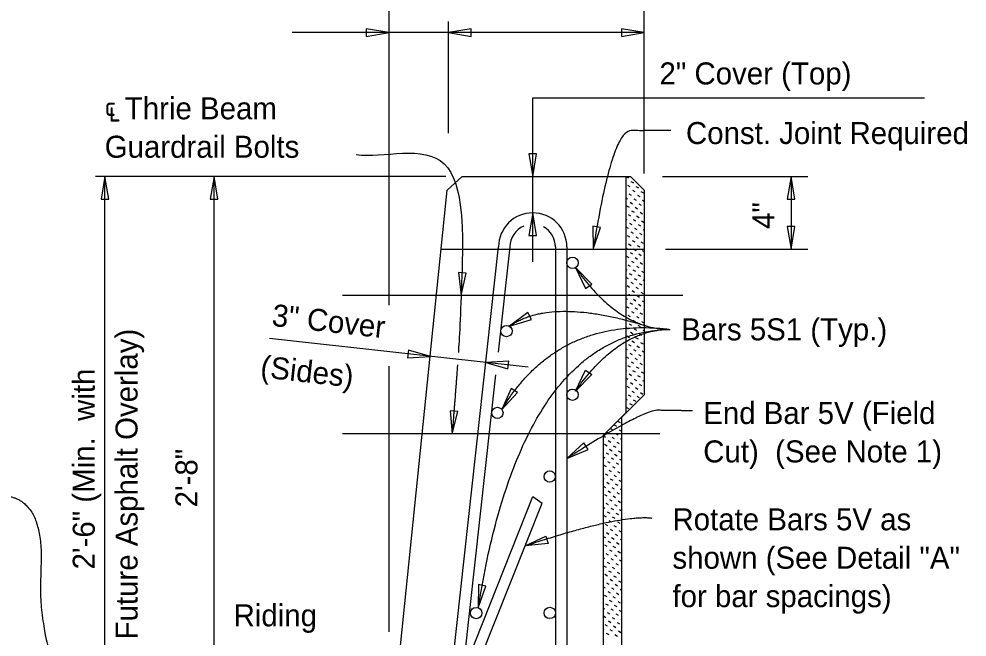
# Model space of a CAD drawing. Extents: x 120632.7 to 120668.8, y 120715.7 to 120740.6.
# Drawn here: x 120645.927 to 120650.27, y 120724.135 to 120726.967 of the extents above; entities that cross this region are included whole.
import ezdxf

# ---------------------------------------------------------------- set-up
doc = ezdxf.new("R2010")
doc.units = 0
for name, color, linetype in [('CL_Minor', 7, 'Continuous'), ('Dimension', 7, 'Continuous'), ('Miscellaneous', 7, 'Continuous'), ('Rebar', 7, 'Continuous'), ('TextStructures', 7, 'Continuous'), ('TrafBarrierConc', 7, 'Continuous')]:
    doc.layers.add(name, color=color, linetype=linetype)

msp = doc.modelspace()

# ---------------------------------------------------------------- linework, layer by layer
at = {"layer": 'CL_Minor'}
for p, q in [((120648.9674, 120725.6995), (120647.4083, 120725.6995)), ((120648.8627, 120725.0664), (120647.4083, 120725.0664))]:
    msp.add_line(p, q, dxfattribs=at)
at = {"layer": 'Dimension'}
for p, q in [((120648.7907, 120726.2582), (120648.7907, 120727.3935)), ((120647.6221, 120725.6558), (120647.6221, 120727.38)), ((120647.8948, 120726.4428), (120647.8948, 120726.9548)), ((120648.7907, 120726.9043), (120647.1778, 120726.9043)), ((120648.2804, 120725.8538), (120648.2804, 120726.6046)), ((120648.2804, 120726.6046), (120650.0749, 120726.6046)), ((120647.8818, 120726.2451), (120646.2774, 120726.2451)), ((120646.3205, 120722.7748), (120646.3205, 120726.2451)), ((120646.8205, 120723.5784), (120646.8205, 120726.2451)), ((120648.8745, 120726.2451), (120649.5403, 120726.2451)), ((120649.4639, 120726.2451), (120649.4639, 120725.9118)), ((120648.888, 120725.9118), (120649.5403, 120725.9118)), ((120648.26, 120725.3711), (120647.0749, 120725.5022)), ((120647.6221, 120724.1579), (120647.6221, 120725.3756))]:
    msp.add_line(p, q, dxfattribs=at)
for points in [[(120647.6221, 120726.9043), (120647.518, 120726.922), (120647.518, 120726.8867)], [(120647.8948, 120726.9043), (120647.999, 120726.8867), (120647.999, 120726.922)], [(120648.7907, 120726.9043), (120648.6866, 120726.922), (120648.6866, 120726.8867)], [(120648.2803, 120726.2451), (120648.298, 120726.3492), (120648.2627, 120726.3492)], [(120646.3205, 120726.2451), (120646.3029, 120726.141), (120646.3382, 120726.141)], [(120646.8205, 120726.2451), (120646.8029, 120726.141), (120646.8382, 120726.141)], [(120649.4639, 120726.2451), (120649.4463, 120726.141), (120649.4815, 120726.141)], [(120648.2803, 120726.0784), (120648.2627, 120725.9743), (120648.298, 120725.9743)], [(120648.5572, 120725.9118), (120648.5909, 120726.0119), (120648.556, 120726.0174)], [(120649.4639, 120725.9118), (120649.4815, 120726.0159), (120649.4463, 120726.0159)], [(120647.9523, 120725.6995), (120647.9759, 120725.8025), (120647.9407, 120725.8045)], [(120648.4766, 120725.8273), (120648.5215, 120725.7317), (120648.5505, 120725.7519)], [(120648.1733, 120725.559), (120648.2744, 120725.5897), (120648.2586, 120725.6213)], [(120647.8126, 120725.4206), (120647.711, 120725.4493), (120647.7072, 120725.4142)], [(120648.0655, 120725.3927), (120648.167, 120725.3636), (120648.1709, 120725.3986)], [(120648.4766, 120725.2619), (120648.5215, 120725.3574), (120648.5505, 120725.3373)], [(120648.1389, 120725.1777), (120648.2112, 120725.2547), (120648.1819, 120725.2742)], [(120647.9113, 120725.0664), (120647.937, 120725.1688), (120647.9018, 120725.1716)], [(120648.4366, 120724.9535), (120648.534, 120724.9943), (120648.5152, 120725.0241)], [(120648.2454, 120724.5524), (120648.3409, 120724.5976), (120648.3504, 120724.5636)], [(120648.0305, 120724.2692), (120648.0663, 120724.3685), (120648.0316, 120724.3748)]]:
    msp.add_lwpolyline(points, close=True, dxfattribs=at)
for points, degree in [([(120648.9127, 120726.4549), (120648.8182, 120726.4549), (120648.6428, 120726.4549), (120648.5573, 120725.9118)], 2), ([(120647.4722, 120726.3456), (120647.593, 120726.328), (120647.9728, 120726.4564), (120647.9564, 120725.7274), (120647.9432, 120725.4917), (120647.9397, 120725.4389)], 3), ([(120648.4766, 120725.8273), (120648.6732, 120725.5446), (120648.9099, 120725.5446)], 2), ([(120648.1733, 120725.559), (120648.3674, 120725.6953), (120648.8048, 120725.5591)], 2), ([(120648.0306, 120724.2692), (120648.2328, 120725.531), (120648.9099, 120725.5446)], 2), ([(120648.1389, 120725.1777), (120648.4004, 120725.6071), (120648.9099, 120725.5446)], 2), ([(120648.4766, 120725.2619), (120648.6732, 120725.5446), (120648.9099, 120725.5446)], 2), ([(120647.9357, 120725.3814), (120647.9298, 120725.299), (120647.9221, 120725.2049), (120647.9114, 120725.0664)], 2), ([(120649.0118, 120725.1718), (120648.9151, 120725.1718), (120648.7891, 120725.1763), (120648.4366, 120724.9535)], 2), ([(120645.8334, 120724.7826), (120646.0481, 120724.7906), (120646.0065, 120724.0831), (120646.2035, 120723.7451)], 2), ([(120648.2455, 120724.5524), (120648.6769, 120724.6971), (120648.8256, 120724.6801)], 2)]:
    msp.add_open_spline(points, degree=degree, dxfattribs=at)
at = {"layer": 'Miscellaneous'}
for p, q in [((120648.7073, 120726.2451), (120648.7073, 120725.1617)), ((120648.7073, 120726.2451), (120648.7185, 120726.2386)), ((120648.7303, 120726.2221), (120648.7415, 120726.2156)), ((120648.7073, 120726.1833), (120648.7085, 120726.1826)), ((120648.7138, 120726.2056), (120648.725, 120726.1991)), ((120648.7368, 120726.1826), (120648.748, 120726.1762)), ((120648.7533, 120726.1991), (120648.7645, 120726.1927)), ((120648.7073, 120726.1476), (120648.715, 120726.1432)), ((120648.7203, 120726.1661), (120648.7315, 120726.1597)), ((120648.7433, 120726.1432), (120648.7545, 120726.1367)), ((120648.7598, 120726.1597), (120648.771, 120726.1532)), ((120648.7763, 120726.1762), (120648.7875, 120726.1697)), ((120648.7828, 120726.1367), (120648.7907, 120726.1321)), ((120648.7103, 120726.1102), (120648.7215, 120726.1037)), ((120648.7268, 120726.1267), (120648.738, 120726.1202)), ((120648.7498, 120726.1037), (120648.761, 120726.0972)), ((120648.7663, 120726.1202), (120648.7775, 120726.1137)), ((120648.7893, 120726.0972), (120648.7907, 120726.0964)), ((120648.7073, 120726.0501), (120648.7115, 120726.0477)), ((120648.7168, 120726.0707), (120648.728, 120726.0642)), ((120648.7333, 120726.0872), (120648.7445, 120726.0807)), ((120648.7398, 120726.0477), (120648.7509, 120726.0412)), ((120648.7563, 120726.0642), (120648.7674, 120726.0577)), ((120648.7728, 120726.0807), (120648.7839, 120726.0742)), ((120648.7073, 120726.0144), (120648.718, 120726.0082)), ((120648.7233, 120726.0312), (120648.7345, 120726.0247)), ((120648.7462, 120726.0082), (120648.7574, 120726.0017)), ((120648.7627, 120726.0247), (120648.7739, 120726.0182)), ((120648.7792, 120726.0412), (120648.7904, 120726.0347)), ((120648.7132, 120725.9752), (120648.7244, 120725.9687)), ((120648.7297, 120725.9917), (120648.7409, 120725.9852)), ((120648.7527, 120725.9687), (120648.7639, 120725.9623)), ((120648.7692, 120725.9852), (120648.7804, 120725.9788)), ((120648.7857, 120726.0017), (120648.7907, 120725.9989)), ((120648.7073, 120725.9526), (120648.7079, 120725.9522)), ((120648.7073, 120725.9169), (120648.7144, 120725.9128)), ((120648.7197, 120725.9357), (120648.7309, 120725.9293)), ((120648.7362, 120725.9522), (120648.7474, 120725.9458)), ((120648.7592, 120725.9293), (120648.7704, 120725.9228)), ((120648.7757, 120725.9458), (120648.7869, 120725.9393)), ((120648.7097, 120725.8798), (120648.7209, 120725.8733)), ((120648.7262, 120725.8963), (120648.7374, 120725.8898)), ((120648.7427, 120725.9128), (120648.7539, 120725.9063)), ((120648.7492, 120725.8733), (120648.7604, 120725.8668)), ((120648.7657, 120725.8898), (120648.7769, 120725.8833)), ((120648.7822, 120725.9063), (120648.7907, 120725.9014)), ((120648.7162, 120725.8403), (120648.7274, 120725.8338)), ((120648.7327, 120725.8568), (120648.7439, 120725.8503)), ((120648.7557, 120725.8338), (120648.7669, 120725.8273)), ((120648.7722, 120725.8503), (120648.7834, 120725.8438)), ((120648.7887, 120725.8668), (120648.7907, 120725.8656)), ((120648.7073, 120725.8194), (120648.7109, 120725.8173)), ((120648.7227, 120725.8008), (120648.7339, 120725.7943)), ((120648.7392, 120725.8173), (120648.7504, 120725.8108)), ((120648.7621, 120725.7943), (120648.7733, 120725.7878)), ((120648.7786, 120725.8108), (120648.7898, 120725.8043)), ((120648.7073, 120725.7836), (120648.7174, 120725.7778)), ((120648.7126, 120725.7448), (120648.7238, 120725.7383)), ((120648.7291, 120725.7613), (120648.7403, 120725.7548)), ((120648.7456, 120725.7778), (120648.7568, 120725.7713)), ((120648.7686, 120725.7548), (120648.7798, 120725.7484)), ((120648.7851, 120725.7713), (120648.7907, 120725.7681)), ((120648.7191, 120725.7053), (120648.7303, 120725.6989)), ((120648.7356, 120725.7218), (120648.7468, 120725.7154)), ((120648.7521, 120725.7383), (120648.7633, 120725.7319)), ((120648.7751, 120725.7154), (120648.7863, 120725.7089)), ((120648.7073, 120725.6861), (120648.7138, 120725.6824)), ((120648.7256, 120725.6659), (120648.7368, 120725.6594)), ((120648.7421, 120725.6824), (120648.7533, 120725.6759)), ((120648.7586, 120725.6989), (120648.7698, 120725.6924)), ((120648.7651, 120725.6594), (120648.7763, 120725.6529)), ((120648.7816, 120725.6759), (120648.7907, 120725.6706)), ((120648.7091, 120725.6494), (120648.7203, 120725.6429)), ((120648.7321, 120725.6264), (120648.7433, 120725.6199)), ((120648.7486, 120725.6429), (120648.7598, 120725.6364)), ((120648.7716, 120725.6199), (120648.7828, 120725.6134)), ((120648.7881, 120725.6364), (120648.7907, 120725.6349)), ((120648.7073, 120725.5886), (120648.7103, 120725.5869)), ((120648.7156, 120725.6099), (120648.7268, 120725.6034)), ((120648.7221, 120725.5704), (120648.7333, 120725.5639)), ((120648.7386, 120725.5869), (120648.7498, 120725.5804)), ((120648.7551, 120725.6034), (120648.7663, 120725.5969)), ((120648.7781, 120725.5804), (120648.7893, 120725.5739)), ((120648.7073, 120725.5529), (120648.7168, 120725.5474)), ((120648.7286, 120725.5309), (120648.7398, 120725.5244)), ((120648.7451, 120725.5474), (120648.7563, 120725.5409)), ((120648.7616, 120725.5639), (120648.7728, 120725.5574)), ((120648.7845, 120725.5409), (120648.7907, 120725.5374)), ((120648.7121, 120725.5144), (120648.7233, 120725.5079)), ((120648.735, 120725.4914), (120648.7462, 120725.485)), ((120648.7515, 120725.5079), (120648.7627, 120725.5015)), ((120648.768, 120725.5244), (120648.7792, 120725.518)), ((120648.7745, 120725.485), (120648.7857, 120725.4785)), ((120648.7073, 120725.4554), (120648.7132, 120725.452)), ((120648.7185, 120725.4749), (120648.7297, 120725.4685)), ((120648.7415, 120725.452), (120648.7527, 120725.4455)), ((120648.758, 120725.4685), (120648.7692, 120725.462)), ((120648.781, 120725.4455), (120648.7907, 120725.4399)), ((120648.7085, 120725.419), (120648.7197, 120725.4125)), ((120648.725, 120725.4355), (120648.7362, 120725.429)), ((120648.7315, 120725.396), (120648.7427, 120725.3895)), ((120648.748, 120725.4125), (120648.7592, 120725.406)), ((120648.7645, 120725.429), (120648.7757, 120725.4225)), ((120648.7875, 120725.406), (120648.7907, 120725.4042)), ((120648.7073, 120725.3579), (120648.7097, 120725.3565)), ((120648.715, 120725.3795), (120648.7262, 120725.373)), ((120648.738, 120725.3565), (120648.7492, 120725.35)), ((120648.7545, 120725.373), (120648.7657, 120725.3665)), ((120648.771, 120725.3895), (120648.7822, 120725.383)), ((120648.7073, 120725.3221), (120648.7162, 120725.317)), ((120648.7215, 120725.34), (120648.7327, 120725.3335)), ((120648.7445, 120725.317), (120648.7557, 120725.3105)), ((120648.761, 120725.3335), (120648.7722, 120725.327)), ((120648.7775, 120725.35), (120648.7887, 120725.3435)), ((120648.7839, 120725.3105), (120648.7907, 120725.3066)), ((120648.7115, 120725.284), (120648.7227, 120725.2775)), ((120648.728, 120725.3005), (120648.7392, 120725.294)), ((120648.7509, 120725.2775), (120648.7621, 120725.2711)), ((120648.7674, 120725.294), (120648.7786, 120725.2876)), ((120648.7904, 120725.2711), (120648.7907, 120725.2709)), ((120648.7073, 120725.2246), (120648.7126, 120725.2216)), ((120648.718, 120725.2445), (120648.7291, 120725.2381)), ((120648.7345, 120725.261), (120648.7456, 120725.2546)), ((120648.7409, 120725.2216), (120648.7521, 120725.2151)), ((120648.7574, 120725.2381), (120648.7686, 120725.2316)), ((120648.7739, 120725.2546), (120648.7851, 120725.2481)), ((120648.7079, 120725.1886), (120648.7191, 120725.1821)), ((120648.7244, 120725.2051), (120648.7356, 120725.1986)), ((120648.7073, 120725.1617), (120648.6032, 120725.0576)), ((120648.6857, 120725.14), (120648.6865, 120725.1396)), ((120648.6527, 120725.107), (120648.6639, 120725.1006)), ((120648.6692, 120725.1235), (120648.6804, 120725.1171)), ((120648.6032, 120725.0576), (120648.6032, 120724.8007)), ((120648.6032, 120725.0576), (120648.6144, 120725.0511)), ((120648.6197, 120725.0741), (120648.6309, 120725.0676)), ((120648.6362, 120725.0906), (120648.6474, 120725.0841)), ((120648.6427, 120725.0511), (120648.6539, 120725.0446)), ((120648.6592, 120725.0676), (120648.6704, 120725.0611)), ((120648.6757, 120725.0841), (120648.6865, 120725.0778)), ((120648.6097, 120725.0181), (120648.6209, 120725.0116)), ((120648.6262, 120725.0346), (120648.6374, 120725.0281)), ((120648.6491, 120725.0116), (120648.6603, 120725.0051)), ((120648.6656, 120725.0281), (120648.6768, 120725.0216)), ((120648.6821, 120725.0446), (120648.6865, 120725.0421)), ((120648.6032, 120724.9958), (120648.6044, 120724.9951)), ((120648.6161, 120724.9786), (120648.6273, 120724.9721)), ((120648.6326, 120724.9951), (120648.6438, 120724.9886)), ((120648.6556, 120724.9721), (120648.6668, 120724.9656)), ((120648.6721, 120724.9886), (120648.6833, 120724.9821)), ((120648.6032, 120724.96), (120648.6108, 120724.9556)), ((120648.6061, 120724.9226), (120648.6173, 120724.9161)), ((120648.6226, 120724.9391), (120648.6338, 120724.9326)), ((120648.6391, 120724.9556), (120648.6503, 120724.9491)), ((120648.6621, 120724.9326), (120648.6733, 120724.9261)), ((120648.6786, 120724.9491), (120648.6865, 120724.9446)), ((120648.6126, 120724.8831), (120648.6238, 120724.8767)), ((120648.6291, 120724.8996), (120648.6403, 120724.8931)), ((120648.6456, 120724.9161), (120648.6568, 120724.9096)), ((120648.6521, 120724.8767), (120648.6633, 120724.8702)), ((120648.6686, 120724.8931), (120648.6798, 120724.8867)), ((120648.6851, 120724.9096), (120648.6865, 120724.9088)), ((120648.6032, 120724.8625), (120648.6073, 120724.8602)), ((120648.6191, 120724.8437), (120648.6303, 120724.8372)), ((120648.6356, 120724.8602), (120648.6468, 120724.8537)), ((120648.6586, 120724.8372), (120648.6698, 120724.8307)), ((120648.6751, 120724.8537), (120648.6863, 120724.8472)), ((120648.6032, 120724.8268), (120648.6138, 120724.8207)), ((120648.6032, 120724.8007), (120648.6032, 120724.0249)), ((120648.6091, 120724.7877), (120648.6203, 120724.7812)), ((120648.6256, 120724.8042), (120648.6368, 120724.7977)), ((120648.6421, 120724.8207), (120648.6533, 120724.8142)), ((120648.665, 120724.7977), (120648.6762, 120724.7912)), ((120648.6815, 120724.8142), (120648.6865, 120724.8113)), ((120648.6032, 120724.765), (120648.6038, 120724.7647)), ((120648.6156, 120724.7482), (120648.6267, 120724.7417)), ((120648.6321, 120724.7647), (120648.6432, 120724.7582)), ((120648.6486, 120724.7812), (120648.6597, 120724.7747)), ((120648.6715, 120724.7582), (120648.6827, 120724.7517)), ((120648.6032, 120724.7293), (120648.6102, 120724.7252)), ((120648.622, 120724.7087), (120648.6332, 120724.7022)), ((120648.6385, 120724.7252), (120648.6497, 120724.7187)), ((120648.655, 120724.7417), (120648.6662, 120724.7352)), ((120648.6615, 120724.7022), (120648.6727, 120724.6957)), ((120648.678, 120724.7187), (120648.6865, 120724.7138)), ((120648.6055, 120724.6922), (120648.6167, 120724.6857)), ((120648.6285, 120724.6692), (120648.6397, 120724.6628)), ((120648.645, 120724.6857), (120648.6562, 120724.6792)), ((120648.668, 120724.6628), (120648.6792, 120724.6563)), ((120648.6845, 120724.6792), (120648.6865, 120724.6781)), ((120648.6032, 120724.6318), (120648.6067, 120724.6298)), ((120648.612, 120724.6527), (120648.6232, 120724.6463)), ((120648.635, 120724.6298), (120648.6462, 120724.6233)), ((120648.6515, 120724.6463), (120648.6627, 120724.6398)), ((120648.6745, 120724.6233), (120648.6857, 120724.6168)), ((120648.6032, 120724.5961), (120648.6132, 120724.5903)), ((120648.6185, 120724.6133), (120648.6297, 120724.6068)), ((120648.625, 120724.5738), (120648.6362, 120724.5673)), ((120648.6415, 120724.5903), (120648.6527, 120724.5838)), ((120648.658, 120724.6068), (120648.6692, 120724.6003)), ((120648.681, 120724.5838), (120648.6865, 120724.5806)), ((120648.6085, 120724.5573), (120648.6197, 120724.5508)), ((120648.6315, 120724.5343), (120648.6427, 120724.5278)), ((120648.648, 120724.5508), (120648.6592, 120724.5443)), ((120648.6645, 120724.5673), (120648.6757, 120724.5608)), ((120648.6709, 120724.5278), (120648.6821, 120724.5213)), ((120648.6032, 120724.4986), (120648.6097, 120724.4948)), ((120648.615, 120724.5178), (120648.6262, 120724.5113)), ((120648.6379, 120724.4948), (120648.6491, 120724.4883)), ((120648.6544, 120724.5113), (120648.6656, 120724.5048)), ((120648.6774, 120724.4883), (120648.6865, 120724.4831)), ((120648.6049, 120724.4618), (120648.6161, 120724.4553)), ((120648.6214, 120724.4783), (120648.6326, 120724.4718)), ((120648.6444, 120724.4553), (120648.6556, 120724.4489)), ((120648.6609, 120724.4718), (120648.6721, 120724.4654)), ((120648.6839, 120724.4489), (120648.6865, 120724.4473)), ((120648.6032, 120724.4011), (120648.6061, 120724.3994)), ((120648.6114, 120724.4223), (120648.6226, 120724.4159)), ((120648.6279, 120724.4388), (120648.6391, 120724.4324)), ((120648.6344, 120724.3994), (120648.6456, 120724.3929)), ((120648.6509, 120724.4159), (120648.6621, 120724.4094)), ((120648.6674, 120724.4324), (120648.6786, 120724.4259)), ((120648.6032, 120724.3653), (120648.6126, 120724.3599)), ((120648.6179, 120724.3829), (120648.6291, 120724.3764)), ((120648.6409, 120724.3599), (120648.6521, 120724.3534)), ((120648.6574, 120724.3764), (120648.6686, 120724.3699)), ((120648.6739, 120724.3929), (120648.6851, 120724.3864)), ((120648.6804, 120724.3534), (120648.6865, 120724.3498)), ((120648.6079, 120724.3269), (120648.6191, 120724.3204)), ((120648.6244, 120724.3434), (120648.6356, 120724.3369)), ((120648.6474, 120724.3204), (120648.6586, 120724.3139)), ((120648.6639, 120724.3369), (120648.6751, 120724.3304)), ((120648.6032, 120724.2678), (120648.6091, 120724.2644)), ((120648.6144, 120724.2874), (120648.6256, 120724.2809)), ((120648.6309, 120724.3039), (120648.6421, 120724.2974)), ((120648.6539, 120724.2809), (120648.665, 120724.2744)), ((120648.6704, 120724.2974), (120648.6815, 120724.2909)), ((120648.6044, 120724.2314), (120648.6156, 120724.2249)), ((120648.6209, 120724.2479), (120648.6321, 120724.2414)), ((120648.6374, 120724.2644), (120648.6486, 120724.2579)), ((120648.6438, 120724.2249), (120648.655, 120724.2185)), ((120648.6603, 120724.2414), (120648.6715, 120724.235)), ((120648.6768, 120724.2579), (120648.6865, 120724.2523)), ((120648.6108, 120724.1919), (120648.622, 120724.1855)), ((120648.6273, 120724.2084), (120648.6385, 120724.202)), ((120648.6503, 120724.1855), (120648.6615, 120724.179)), ((120648.6668, 120724.202), (120648.678, 120724.1955)), ((120648.6833, 120724.2185), (120648.6865, 120724.2166)), ((120648.6032, 120724.1703), (120648.6055, 120724.169)), ((120648.6173, 120724.1525), (120648.6285, 120724.146)), ((120648.6338, 120724.169), (120648.645, 120724.1625)), ((120648.6568, 120724.146), (120648.668, 120724.1395)), ((120648.6733, 120724.1625), (120648.6845, 120724.156))]:
    msp.add_line(p, q, dxfattribs=at)
at = {"layer": 'Rebar'}
for p, q in [((120647.8906, 120723.8122), (120648.124, 120725.9221)), ((120648.1231, 120725.4399), (120648.1765, 120725.922)), ((120648.3845, 120725.9221), (120648.3845, 120723.2346)), ((120648.4366, 120725.9221), (120648.4366, 120723.2324)), ((120647.945, 120723.8295), (120648.1117, 120725.3363)), ((120647.9608, 120723.9726), (120648.2807, 120724.7782)), ((120647.9621, 120723.8389), (120648.3231, 120724.748)), ((120648.2807, 120724.7782), (120648.3231, 120724.748))]:
    msp.add_line(p, q, dxfattribs=at)
for centre in [(120648.4626, 120725.8492), (120648.16, 120725.5367), (120648.4626, 120725.2451), (120648.1184, 120725.1617), (120648.3584, 120724.8701), (120648.0212, 120724.2449), (120648.3585, 120724.245)]:
    msp.add_circle(centre, 0.026, dxfattribs=at)
for radius, start, end in [(0.1563, 0, 179.9996), (0.1042, 113.3834, 179.9996), (0.1042, 0, 61.7951)]:
    msp.add_arc((120648.2804, 120725.9221), radius, start, end, dxfattribs=at)
at = {"layer": 'TrafBarrierConc'}
for p, q in [((120647.8885, 120726.1829), (120647.9573, 120726.2451)), ((120647.9574, 120726.2451), (120648.7282, 120726.2451)), ((120648.7282, 120726.2451), (120648.7907, 120726.1826)), ((120647.6221, 120723.5784), (120647.8885, 120726.1829)), ((120648.7907, 120726.1826), (120648.7907, 120725.2451)), ((120647.8608, 120725.9118), (120648.7907, 120725.9118)), ((120648.7907, 120725.2451), (120648.6865, 120725.1409)), ((120648.6865, 120725.1409), (120648.6865, 120723.5784))]:
    msp.add_line(p, q, dxfattribs=at)

# ---------------------------------------------------------------- texts
at = {"layer": 'Dimension'}
for s, p in [('℄ Thrie Beam ', (120646.3198, 120726.5068)), ('Guardrail Bolts', (120646.3198, 120726.3308)), ('End Bar 5V (Field ', (120649.0613, 120725.1109)), ('Cut)  (See Note 1)', (120649.0613, 120724.9349)), ('Rotate Bars 5V as ', (120648.9204, 120724.6238)), ('shown (See Detail "A" ', (120648.9204, 120724.4478)), ('for bar spacings)', (120648.9204, 120724.2718)), ('Riding ', (120646.9101, 120724.1839))]:
    msp.add_text(s, height=0.1008, dxfattribs=at).set_placement(p)
at = {"layer": 'TextStructures'}
for s, p in [('2" Cover (Top)', (120648.861, 120726.6668)), ('Const. Joint Required', (120648.9822, 120726.3936)), ('Bars 5S1 (Typ.)', (120648.9602, 120725.4941))]:
    msp.add_text(s, height=0.1008, dxfattribs=at).set_placement(p)
for s, rotation, p in [('4"', 90, (120649.3878, 120726.0045)), ('3" Cover', 353.6878, (120647.0822, 120725.5609)), ('Future Asphalt Overlay)', 90, (120646.4703, 120724.1239)), ('(Sides)', 353.6878, (120647.0296, 120725.3251)), ('2\'-6" (Min.  with', 90, (120646.2742, 120724.4446)), ('2\'-8"', 90, (120646.7446, 120724.7289))]:
    msp.add_text(s, height=0.1008, rotation=rotation, dxfattribs=at).set_placement(p)

doc.saveas('drawing.dxf')
